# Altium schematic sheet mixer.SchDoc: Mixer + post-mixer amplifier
size A4; Engineer: CT; SheetNumber: 1; SheetTotal: 1
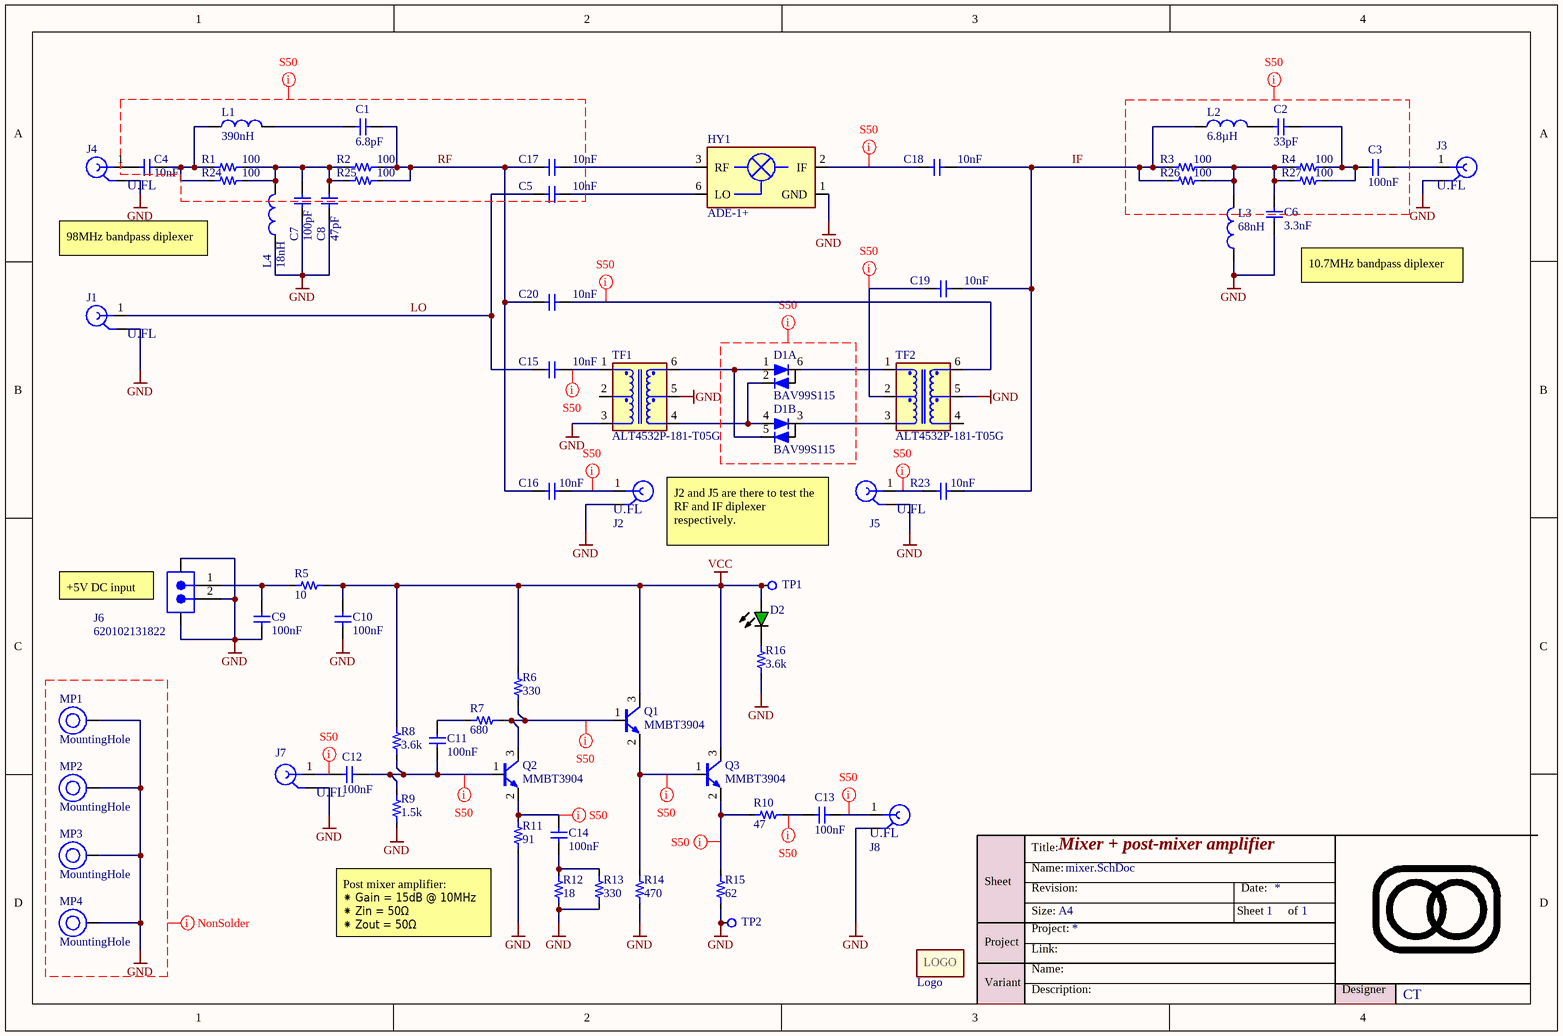
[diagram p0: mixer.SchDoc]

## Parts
C1  value 6.8pF  [0603-C-N]  (hidden comment: Capacitor 6.8pF +/-0.5pF 50V NP0 0603)
C2  value 33pF  [0603-C-N]  (hidden comment: Capacitor 33pF +/-1% 50V NP0 0603)
C3  value 100nF  [0603-C-N]  (hidden comment: Capacitor 100nF +/-10% 50V X7R 0603)
C4  value 10nF  [0603-C-N]  (hidden comment: Capacitor 10nF 50V NP0 0603)
C5  value 10nF  [0603-C-N]  (hidden comment: Capacitor 10nF 50V NP0 0603)
C6  value 3.3nF  [0603-C-N]  (hidden comment: Capacitor 3.3nF +/-10% 50V X7R 0603)
C7  value 100pF  [0603-C-N]  (hidden comment: Capacitor 100pF +/-5% 50V NP0 0603)
C8  value 47pF  [0603-C-N]  (hidden comment: Capacitor 47pF +/-5% 50V C0G 0603)
C9  value 100nF  [0603-C-N]  (hidden comment: Capacitor 100nF +/-10% 50V X7R 0603)
C10  value 100nF  [0603-C-N]  (hidden comment: Capacitor 100nF +/-10% 50V X7R 0603)
C11  value 100nF  [0603-C-N]  (hidden comment: Capacitor 100nF +/-10% 50V X7R 0603)
C12  value 100nF  [0603-C-N]  (hidden comment: Capacitor 100nF +/-10% 50V X7R 0603)
C13  value 100nF  [0603-C-N]  (hidden comment: Capacitor 100nF +/-10% 50V X7R 0603)
C14  value 100nF  [0603-C-N]  (hidden comment: Capacitor 100nF +/-10% 50V X7R 0603)
C15  value 10nF  [0603-C-N]  (hidden comment: Capacitor 10nF 50V NP0 0603)
C16  value 10nF  [0603-C-N]  (hidden comment: Capacitor 10nF 50V NP0 0603)
C17  value 10nF  [0603-C-N]  (hidden comment: Capacitor 10nF 50V NP0 0603)
C18  value 10nF  [0603-C-N]  (hidden comment: Capacitor 10nF 50V NP0 0603)
C19  value 10nF  [0603-C-N]  (hidden comment: Capacitor 10nF 50V NP0 0603)
C20  value 10nF  [0603-C-N]  (hidden comment: Capacitor 10nF 50V NP0 0603)
D1  BAV99S115  [SOT-363-N]  (parts A,B of 2)
D2  150060GS84000  [WL-SMCW_0603_150060xx8x000]  (value not drawn)
GR1  Logo  [LOGO_9x6mm]  (no BOM)
HY1  ADE-1+  [ADE-1+]
J1  U.FL-R-SMT(10)  [HRS-U.FL-R-SMT_V]  (value not drawn)
J2  U.FL-R-SMT(10)  [HRS-U.FL-R-SMT_V]  (value not drawn)
J3  U.FL-R-SMT(10)  [HRS-U.FL-R-SMT_V]  (value not drawn)
J4  U.FL-R-SMT(10)  [HRS-U.FL-R-SMT_V]  (value not drawn)
J5  U.FL-R-SMT(10)  [HRS-U.FL-R-SMT_V]  (value not drawn)
J6  620102131822  [620102131822]
J7  U.FL-R-SMT(10)  [HRS-U.FL-R-SMT_V]  (value not drawn)
J8  U.FL-R-SMT(10)  [HRS-U.FL-R-SMT_V]  (value not drawn)
L1  Inductance: 390nH  [WE-KI_1008]  (hidden comment: 744762239GA)
L2  Inductance: 6.8µH  [WE-RFH_1008A]  (hidden comment: 744758368A)
L3  Inductance: 68nH  [WE-KI_1008]  (hidden comment: 744762168GA)
L4  Inductance: 18nH  [WE-KI_1008]  (hidden comment: 744762118A)
MP1  MountingHole  [PTH-M3D6.5_VIA-RING]  (no BOM)
MP2  MountingHole  [PTH-M3D6.5_VIA-RING]  (no BOM)
MP3  MountingHole  [PTH-M3D6.5_VIA-RING]  (no BOM)
MP4  MountingHole  [PTH-M3D6.5_VIA-RING]  (no BOM)
Q1  MMBT3904  [SOT-23-3-N]
Q2  MMBT3904  [SOT-23-3-N]
Q3  MMBT3904  [SOT-23-3-N]
R1  value 100  [0603-R-N]  (hidden comment: Resistor 100R +/-1% 50V 0603)
R2  value 100  [0603-R-N]  (hidden comment: Resistor 100R +/-1% 50V 0603)
R3  value 100  [0603-R-N]  (hidden comment: Resistor 100R +/-1% 50V 0603)
R4  value 100  [0603-R-N]  (hidden comment: Resistor 100R +/-1% 50V 0603)
R5  value 10  [0603-R-N]  (hidden comment: Resistor 10R +/-1% 50V 0603)
R6  value 330  [0603-R-N]  (hidden comment: Resistor 330R +/-1% 50V 0603)
R7  value 680  [0603-R-N]  (hidden comment: Resistor 680R +/-1% 0.1W 0603)
R8  value 3.6k  [0603-R-N]  (hidden comment: Resistor 3.6k +/-0.1W 1% 0603)
R9  value 1.5k  [0603-R-N]  (hidden comment: Resistor 1.5k +/-1% 50V 0603)
R10  value 47  [0603-R-N]  (hidden comment: Resistor 47R +/-1% 0.1W 0603)
R11  value 91  [0603-R-N]  (hidden comment: Resistor 91R +/-1% 0.1W 0603)
R12  value 18  [0603-R-N]  (hidden comment: Resistor 18R +/-1% 0.1W 0603)
R13  value 330  [0603-R-N]  (hidden comment: Resistor 330R +/-1% 50V 0603)
R14  value 470  [0603-R-N]  (hidden comment: Resistor 470R +/-1% 50V 0603)
R15  value 62  [0603-R-N]  (hidden comment: Resistor 62R +/-1% 0.1W 0603)
R16  value 3.6k  [0603-R-N]  (hidden comment: Resistor 3.6k +/-0.1W 1% 0603)
R23  value 10nF  [0603-C-N]  (hidden comment: Capacitor 10nF 50V NP0 0603)
R24  value 100  [0603-R-N]  (hidden comment: Resistor 100R +/-1% 50V 0603)
R25  value 100  [0603-R-N]  (hidden comment: Resistor 100R +/-1% 50V 0603)
R26  value 100  [0603-R-N]  (hidden comment: Resistor 100R +/-1% 50V 0603)
R27  value 100  [0603-R-N]  (hidden comment: Resistor 100R +/-1% 50V 0603)
TF1  ALT4532P-181-T05G  [TF_STD_LAN1000_4532_6P]
TF2  ALT4532P-181-T05G  [TF_STD_LAN1000_4532_6P]
TP1  Testpad with multiple sizes  [TP_1.5mm_0.3mmHole]  (value not drawn)  (no BOM)
TP2  Testpad with multiple sizes  [TP_1.5mm_0.3mmHole]  (value not drawn)  (no BOM)

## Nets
GND: C6.1 C7.1 C8.1 C9.1 C10.1 HY1.1(GND) J1.2(GND) J2.2(GND) J3.2(GND) J4.2(GND) J5.2(GND) J6.2 J6.MP1 J6.MP2 J7.2(GND) J8.2(GND) L3.1 L4.1 MP1.1(H1) MP2.1(H1) MP3.1(H1) MP4.1(H1) R9.1 R11.1 R12.1 R13.1 R14.1 R15.1 R16.1 TF1.3(Sec1+) TF1.5(Sec1-) TF2.5(Sec1-) TP2.1(Pad)
VCC: C10.2 D2.2(A) Q1.3(C) Q3.3(C) R5.2 R6.2 R8.2 TP1.1(Pad)
IF: C18.2 C19.2 L2.1 R3.1 R23.2 R26.1
LO: C5.1 C15.1 J1.1(SIG)
RF: C1.2 C16.1 C17.1 C20.1 R2.2 R25.2
NetC1_1: C1.1 L1.2
NetC2_1: C2.1 L2.2
NetC2_2: C2.2 C3.2 R4.2 R27.2
NetC3_1: C3.1 J3.1(SIG)
NetC4_1: C4.1 J4.1(SIG)
NetC4_2: C4.2 L1.1 R1.1 R24.1
NetC5_2: C5.2 HY1.6(LO)
NetC6_2: C6.2 L3.2 R3.2 R4.1 R26.2 R27.1
NetC7_2: C7.2 C8.2 L4.2 R1.2 R2.1 R24.2 R25.1
NetC9_2: C9.2 J6.1 R5.1
NetC11_1: C11.1 R7.1
NetC11_2: C11.2 C12.1 Q2.1(B) R8.1 R9.2
NetC12_2: C12.2 J7.1(SIG)
NetC13_1: C13.1 R10.2
NetC13_2: C13.2 J8.1(SIG)
NetC14_1: C14.1 Q2.2(E) R11.2
NetC14_2: C14.2 R12.2 R13.2
NetC15_2: C15.2 TF1.1(Pri1+)
NetC16_2: C16.2 J2.1(SIG)
NetC17_2: C17.2 HY1.3(RF)
NetC18_1: C18.1 HY1.2(IF)
NetC19_1: C19.1 TF2.2(Pri2+)
NetC20_2: C20.2 TF2.6(Pri1-)
NetD1_1: D1.1(A) D1.5(C) TF1.6(Pri1-)
NetD1_2: D1.2(C) D1.4(A) TF1.4(Pri2-)
NetD1_3: D1.3(CA) TF2.3(Sec1+)
NetD1_6: D1.6(CA) TF2.1(Pri1+)
NetD2_1: D2.1(K) R16.2
NetJ5_1: J5.1(SIG) R23.1
NetQ1_1: Q1.1(B) Q2.3(C) R6.1 R7.2
NetQ1_2: Q1.2(E) Q3.1(B) R14.2
NetQ3_2: Q3.2(E) R10.1 R15.2

Not connected (* = marked no-connect by the designer): TF1 2(Pri2+); TF2 4(Pri2-)

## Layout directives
net class S50: (no net found under the mark), GND, NetC11_2, NetC12_2, NetC13_1, NetC13_2, NetC14_1, NetC15_2, NetC16_2, NetC18_1, NetC19_1, NetC20_2, NetJ5_1, NetQ1_1, NetQ1_2, NetQ3_2, RF
CompClassName: NonSolder: GND

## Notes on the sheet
- 98MHz bandpass diplexer
- (near C6) 10.7MHz bandpass diplexer
- J2 and J5 are there to test the RF and IF diplexer respectively.
- (near J6) +5V DC input
- Post mixer amplifier:
  ⁕ Gain = 15dB @ 10MHz
  ⁕ Zin = 50Ω
  ⁕ Zout = 50Ω

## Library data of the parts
C1 = CMP-072-000121-14: WCAP-CSGP Multilayer Ceramic Chip Capacitor, General Purpose, size 0603, NP0, 6.8pF, 50VDC; Capacitor Type: MLCC; Q Factor: 536; Insulation Resistance: 10GO; Technical Reference: NP006036R8D050DFCT10000; Tolerance: 0.5pF
C2 = CMP-001-00146-2: Multilayer Ceramic Capacitor 33 Pf 50 V ½ 1% C0G (NP0) 0603 [1608 Metric]; Page Part #: CCQF330; Dissipation Factor: 0.1%; Insulation Resistance: 10GR
C3 C9-C14 = CMP-001-00017-24: Capacitor MLCC, General Purpose, size 0603, X7R, 100nF, +/-10%, 50V; Page Part #: CCQK104; Tolerance: 10%
C4 C5 C15-C20 R23 = CMP-001-00137-6: Multilayer Ceramic Capacitor, Grm Series, 0.01 F, 5%, C0g / Np0, 50 V, 0603 [1608 Metric]; FLIR Part #: YCAM10N-7; Temperature Coefficient: 30ppm/°C
C6 = CMP-072-000609-13: WCAP-CSGP Multilayer Ceramic Chip Capacitor, General Purpose, size 0603, X7R, 3.3nF, 50VDC; Technical Reference: X7R0603332K050DFCT10000; Capacitor Type: MLCC; Tolerance: 10%; Dissipation Factor: 2.5%; Insulation Resistance: 10GO
C7 = CMP-072-000128-17: WCAP-CSGP Multilayer Ceramic Chip Capacitor, General Purpose, size 0603, NP0, 100pF, 50VDC; Page Part #: CCQJ101; Technical Reference: NP00603101J050DFCT10000; Tolerance: 5%; Insulation Resistance: 10GO; Capacitor Type: MLCC; Q Factor: 1000
C8 = CMP-001-00100-15: Capacitor MLCC, General Purpose, size 0603, C0G, 47pF, +/-5%, 50V; Tolerance: 5%; Temperature Coefficient: 30ppm/°C
D1 = CMP-004-00059-1: Diode-gp Power Switching; Average Rectified Current: 200mA; Max Repetitive Reverse Voltage (Vrrm): 100V; Max Reverse Current: 500nA; Max Forward Surge Current (Ifsm): 4A; Reverse Recovery Time: 4ns; Voltage: 75V
D2 = CMP-002-001076-16: WL-SMCW Mono-color Chip LED Waterclear, size 0603, Green, 3.3V, 40°; Manufacturer: Wurth Elektronik; Page Part #: MOVPA-0270A; Chip Technology: InGaN; Case/Size Code: 0603; Luminous Intensity: 3000mcd; Peak Wavelength: 520nm; Dominant Wavelength: 525nm
HY1 = CMP-00025-00013-3: Double Balanced Mixer, 0.5MHz Min, 500MHz Max, 7.8dB Conversion Loss-Max; pin to pad: 1>1+4+5
J1-J5 J7 J8 = CMP-002-00035-12: Ultra Small Surface Mount Coaxial Connector, 50 Ohm, -40 to 90 degC, 3-Pin SMD, RoHS, Tape and Reel; pin to pad: 1>3 2>1+2; Manufacturer: Hirose Electric; Connector Type: RF&Coax; Impedance: 50Ohm; Value: U.FL
J6 = CMP-047-000040-15: WR-WTB SMT Male Horizontal Shrouded Header, pitch 2mm, 2p; Page Part #: K620102131822; Pin Number: 2; Rated Current: 2A; Contact Resistance: 20mOhm; Value: JST-PH; Withstanding Voltage: 800VAC; Working Voltage: 100VAC
L1 = CMP-051-000215-6: WE-KI SMT Wire Wound Ceramic Inductor, size 1008, 390nH, 0.47A; Manufacturer: Wurth Elektronik; DC Resistance Max: 1.06Ohm; Q Factor: 45; Inductance Tolerance: +/-2%; Case/Size Code: 1008; Self Resonant Frequency: 530MHz
L2 = CMP-003-000840-3: WE-RFH SMT Ferrite Inductor, size 1008A, 6.8µH, 0.36A, 2O; Manufacturer: Wurth Elektronik; Q Factor: 20; Inductance Tolerance: +/-5%; Self Resonant Frequency: 70MHz
L3 = CMP-051-000197-6: WE-KI SMT Wire Wound Ceramic Inductor, size 1008, 68nH, 1A; Manufacturer: Wurth Elektronik; Inductance Tolerance: +/-2%; Case/Size Code: 1008; DC Resistance Max: 0.15Ohm; Q Factor: 60; Self Resonant Frequency: 1300MHz
L4 = CMP-051-000182-6: WE-KI SMT Wire Wound Ceramic Inductor, size 1008, 18nH, 1A; Manufacturer: Wurth Elektronik; Inductance Tolerance: +/-5%; Self Resonant Frequency: 2700MHz; DC Resistance Max: 0.1Ohm; Case/Size Code: 1008; Q Factor: 60
MP1-MP4 = CMP-00028-00004-15: Mounting hole.  Add this so that mounting holes placed in your design don't automagically disappear when you import changes from the schematic.
Q1-Q3 = CMP-014-00026-4: NPN General Purpose Amplifier, 40 V, 0.2 A, -55 to 150 degC, 3-Pin SOT23, RoHS, Tape and Reel; Manufacturer: Fairchild Semiconductor; Elements: 1; Frequency: 300MHz; hFE Min: 100; Vce Max: 300mV; Package Version: Rev. 12, 03/2016; Power: 625mW
R1-R4 R24-R27 = CMP-009-00232-17: Chip Resistor, Thick Film, General Purpose, 0603, 63mW, 50V, 100 Ohm, +/-1%; Temperature Coefficient: 100ppm/°C; Tolerance: 1%; Power Rating: 100mW; Elements: 1
R5 = CMP-009-00230-18: Chip Resistor, Thick Film, General Purpose, 0603, 100mW, 50V, 10 Ohm, +/-1%; Tolerance: 1%; Elements: 1; Temperature Coefficient: 200ppm/°C
R6 R13 = CMP-009-00203-21: Chip Resistor, Thick Film, General Purpose, 0603, 100mW, 50V, 330 Ohm, +/-1%; Page Part #: ROQF3300; Tolerance: 1%; Elements: 1; Temperature Coefficient: 100ppm/°C
R7 = CMP-009-00393-1: SMD Chip Resistor, 680 Ohm, ï¿½ 1%, 100 mW, 0603 [1608 Metric], Thick Film, Precision; Max Power Dissipation: 100mW; Temperature Coefficient: 100ppm/°C; Voltage Rating (DC): 75V
R8 R16 = CMP-009-00405-1: Res Thick Film 0603 3.6K Ohm 1% 0.1W(1/10W) ±100ppm/°C Pad SMD T/R
R9 = CMP-009-00201-21: Chip Resistor, Thick Film, General Purpose, 0603, 100mW, 50V, 1.5 kOhm, +/-1%; Tolerance: 1%; Elements: 1
R10 = CMP-009-00372-5: SMD Chip Resistor, 47 Ohm, ± 1%, 100 mW, 0603 [1608 Metric], Thick Film, General Purpose; Voltage Rating (DC): 50V; Power Rating: 100mW; Temperature Coefficient: 100ppm/°C; Voltage Rating: 75V
R11 = CMP-009-00407-1: SMD Chip Resistor, 91 Ohm, ± 1%, 100 mW, 0603 [1608 Metric], Thick Film, General Purpose; Voltage Rating (DC): 50V; Temperature Coefficient: 100ppm/°C; Max Power Dissipation: 100mW
R12 = CMP-009-00408-1: SMD Chip Resistor, 18 ohm, ï¿½ 1%, 100 mW, 0603 [1608 Metric], Thick Film, General Purpose; Voltage Rating: 50V; Power Rating: 100mW; Temperature Coefficient: 100ppm/°C; Working Voltage: 75V
R14 = CMP-009-00190-23: Chip Resistor, Thick Film, General Purpose, 0603, 100mW, 50V, 470 Ohm, +/-1%; Tolerance: 1%; Elements: 1
R15 = CMP-009-00411-1: Res Thick Film 0603 62 Ohm 1% 1/10W ±100ppm/°C Molded SMD SMD Paper T/R; Max Power Dissipation: 100mW
TF1 TF2 = CMP-142-000004-8: Pulse Transformers and Modules for LAN, Transformer, LxWxH=4.5x3.2x2.9mm; pin to pad: 2>6 3>2 5>3 6>5; FLIR Part #: YTFM1000; Property 1: 100µH; Value: 180uH; Property 2: 8mA; Property 3: 1500Vrms; 3D_model: step; Turns Ratio: 1:1
TP1 TP2 = CMP-027-000000-17: Testpad land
